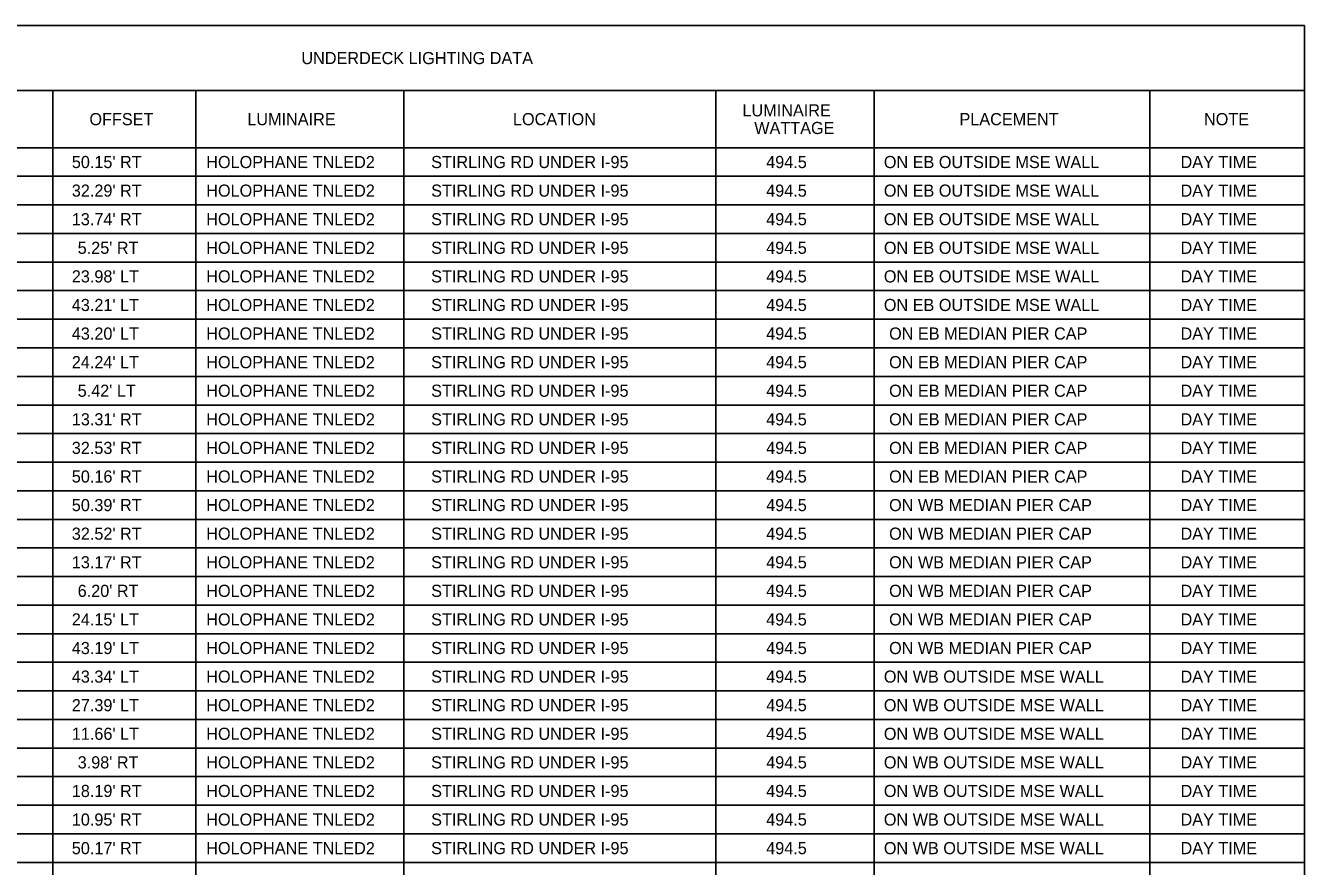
# Model space of a CAD drawing. Extents: x -816.7 to -800.9, y -2209.6 to -2187.8.
# Drawn here: x -810.38 to -803, y -2192.68 to -2187.82 of the extents above; entities that cross this region are included whole.
import ezdxf

# ---------------------------------------------------------------- set-up
doc = ezdxf.new("R2010")
doc.units = 0
for name, color, linetype in [('PlotBorder_dp', 7, 'Continuous'), ('SheetBorder_dp', 7, 'Continuous'), ('SheetLines_dp', 7, 'Continuous'), ('TextMinor', 7, 'Continuous')]:
    doc.layers.add(name, color=color, linetype=linetype)

msp = doc.modelspace()

# ---------------------------------------------------------------- linework, layer by layer
at = {"layer": 'PlotBorder_dp'}
for p, q in [((-810.2186, -2188.1983), (-810.2186, -2189.3533)), ((-810.2186, -2188.1983), (-810.2186, -2195.7208)), ((-809.3936, -2188.1983), (-809.3936, -2195.7208)), ((-809.3936, -2188.1983), (-809.3936, -2195.7208)), ((-808.1936, -2188.1983), (-808.1936, -2195.7208)), ((-808.1936, -2188.1983), (-808.1936, -2195.7208)), ((-806.3936, -2188.1983), (-806.3936, -2195.7208)), ((-806.3936, -2188.1983), (-806.3936, -2195.7208)), ((-805.4786, -2188.1983), (-805.4786, -2195.7208)), ((-805.4786, -2188.1983), (-805.4786, -2195.7208)), ((-813.0161, -2188.5283), (-803.8886, -2188.5283)), ((-810.2186, -2189.5183), (-810.2186, -2195.7208))]:
    msp.add_line(p, q, dxfattribs=at)
at = {"layer": 'SheetLines_dp'}
for p, q in [((-813.0161, -2187.8233), (-802.9961, -2187.8233)), ((-802.9961, -2187.8233), (-802.9961, -2195.7208)), ((-813.0161, -2188.1983), (-802.9961, -2188.1983)), ((-813.0161, -2188.1983), (-802.9961, -2188.1983)), ((-803.8886, -2188.1983), (-803.8886, -2195.7208)), ((-803.8886, -2188.1983), (-803.8886, -2195.7208))]:
    msp.add_line(p, q, dxfattribs=at)
at = {"layer": 'TextMinor'}
for p, q in [((-813.0161, -2188.5283), (-802.9961, -2188.5283)), ((-813.0161, -2188.6933), (-802.9961, -2188.6933)), ((-813.0161, -2188.6933), (-802.9961, -2188.6933)), ((-813.0161, -2188.8583), (-802.9961, -2188.8583)), ((-813.0161, -2188.8583), (-802.9961, -2188.8583)), ((-813.0161, -2189.0233), (-802.9961, -2189.0233)), ((-813.0161, -2189.0233), (-802.9961, -2189.0233)), ((-813.0161, -2189.1883), (-802.9961, -2189.1883)), ((-813.0161, -2189.1883), (-802.9961, -2189.1883)), ((-813.0161, -2189.3533), (-802.9961, -2189.3533)), ((-813.0161, -2189.3533), (-802.9961, -2189.3533)), ((-813.0161, -2189.5183), (-802.9961, -2189.5183)), ((-810.2186, -2189.5183), (-802.9961, -2189.5183)), ((-813.0161, -2189.6833), (-802.9961, -2189.6833)), ((-813.0161, -2189.6833), (-802.9961, -2189.6833)), ((-813.0161, -2189.8483), (-802.9961, -2189.8483)), ((-813.0161, -2189.8483), (-802.9961, -2189.8483)), ((-813.0161, -2190.0133), (-802.9961, -2190.0133)), ((-813.0161, -2190.0133), (-802.9961, -2190.0133)), ((-813.0161, -2190.1783), (-802.9961, -2190.1783)), ((-813.0161, -2190.1783), (-802.9961, -2190.1783)), ((-813.0161, -2190.3433), (-802.9961, -2190.3433)), ((-813.0161, -2190.3433), (-802.9961, -2190.3433)), ((-813.0161, -2190.5083), (-802.9961, -2190.5083)), ((-813.0161, -2190.5083), (-802.9961, -2190.5083)), ((-813.0161, -2190.6733), (-802.9961, -2190.6733)), ((-813.0161, -2190.6733), (-802.9961, -2190.6733)), ((-813.0161, -2190.8383), (-802.9961, -2190.8383)), ((-813.0161, -2190.8383), (-802.9961, -2190.8383)), ((-813.0161, -2191.0033), (-802.9961, -2191.0033)), ((-813.0161, -2191.0033), (-802.9961, -2191.0033)), ((-813.0161, -2191.1683), (-802.9961, -2191.1683)), ((-813.0161, -2191.1683), (-802.9961, -2191.1683)), ((-813.0161, -2191.3333), (-802.9961, -2191.3333)), ((-813.0161, -2191.3333), (-802.9961, -2191.3333)), ((-813.0161, -2191.4983), (-802.9961, -2191.4983)), ((-813.0161, -2191.4983), (-802.9961, -2191.4983)), ((-813.0161, -2191.6633), (-802.9961, -2191.6633)), ((-813.0161, -2191.6633), (-802.9961, -2191.6633)), ((-813.0161, -2191.8283), (-802.9961, -2191.8283)), ((-813.0161, -2191.8283), (-802.9961, -2191.8283)), ((-813.0161, -2191.9933), (-802.9961, -2191.9933)), ((-813.0161, -2191.9933), (-802.9961, -2191.9933)), ((-813.0161, -2192.1583), (-802.9961, -2192.1583)), ((-813.0161, -2192.1583), (-802.9961, -2192.1583)), ((-813.0161, -2192.3233), (-802.9961, -2192.3233)), ((-813.0161, -2192.3233), (-802.9961, -2192.3233)), ((-813.0161, -2192.4883), (-802.9961, -2192.4883)), ((-813.0161, -2192.4883), (-802.9961, -2192.4883)), ((-813.0161, -2192.6533), (-802.9961, -2192.6533)), ((-813.0161, -2192.6533), (-802.9961, -2192.6533))]:
    msp.add_line(p, q, dxfattribs=at)

# ---------------------------------------------------------------- texts
at = {"layer": 'SheetBorder_dp'}
for s, p in [('UNDERDECK LIGHTING DATA', (-808.7843, -2188.0458)), ('LUMINAIRE', (-806.2388, -2188.3473)), ('OFFSET', (-810.0076, -2188.3983)), ('LUMINAIRE', (-809.0963, -2188.3983)), ('LOCATION', (-807.5633, -2188.3983)), ('PLACEMENT', (-804.9867, -2188.3983)), ('NOTE', (-803.5756, -2188.3983)), ('WATTAGE', (-806.171, -2188.4493)), ("50.15' RT", (-810.1092, -2188.6458)), ('HOLOPHANE TNLED2', (-809.3332, -2188.6458)), ('STIRLING RD UNDER I-95', (-808.0355, -2188.6458)), ('494.5', (-806.1021, -2188.6458)), ('ON EB OUTSIDE MSE WALL', (-805.4232, -2188.6458)), ('DAY TIME', (-803.7111, -2188.6458)), ("32.29' RT", (-810.1092, -2188.8108)), ('HOLOPHANE TNLED2', (-809.3332, -2188.8108)), ('STIRLING RD UNDER I-95', (-808.0355, -2188.8108)), ('494.5', (-806.1021, -2188.8108)), ('ON EB OUTSIDE MSE WALL', (-805.4232, -2188.8108)), ('DAY TIME', (-803.7111, -2188.8108)), ("13.74' RT", (-810.1092, -2188.9758)), ('HOLOPHANE TNLED2', (-809.3332, -2188.9758)), ('STIRLING RD UNDER I-95', (-808.0355, -2188.9758)), ('494.5', (-806.1021, -2188.9758)), ('ON EB OUTSIDE MSE WALL', (-805.4232, -2188.9758)), ('DAY TIME', (-803.7111, -2188.9758)), ("5.25' RT", (-810.0753, -2189.1408)), ('HOLOPHANE TNLED2', (-809.3332, -2189.1408)), ('STIRLING RD UNDER I-95', (-808.0355, -2189.1408)), ('494.5', (-806.1021, -2189.1408)), ('ON EB OUTSIDE MSE WALL', (-805.4232, -2189.1408)), ('DAY TIME', (-803.7111, -2189.1408)), ("23.98' LT", (-810.1092, -2189.3058)), ('HOLOPHANE TNLED2', (-809.3332, -2189.3058)), ('STIRLING RD UNDER I-95', (-808.0355, -2189.3058)), ('494.5', (-806.1021, -2189.3058)), ('ON EB OUTSIDE MSE WALL', (-805.4232, -2189.3058)), ('DAY TIME', (-803.7111, -2189.3058)), ("43.21' LT", (-810.1092, -2189.4708)), ('HOLOPHANE TNLED2', (-809.3332, -2189.4708)), ('STIRLING RD UNDER I-95', (-808.0355, -2189.4708)), ('494.5', (-806.1021, -2189.4708)), ('ON EB OUTSIDE MSE WALL', (-805.4232, -2189.4708)), ('DAY TIME', (-803.7111, -2189.4708)), ("43.20' LT", (-810.1092, -2189.6358)), ('HOLOPHANE TNLED2', (-809.3332, -2189.6358)), ('STIRLING RD UNDER I-95', (-808.0355, -2189.6358)), ('494.5', (-806.1021, -2189.6358)), ('ON EB MEDIAN PIER CAP', (-805.3928, -2189.6358)), ('DAY TIME', (-803.7111, -2189.6358)), ("24.24' LT", (-810.1092, -2189.8008)), ('HOLOPHANE TNLED2', (-809.3332, -2189.8008)), ('STIRLING RD UNDER I-95', (-808.0355, -2189.8008)), ('494.5', (-806.1021, -2189.8008)), ('ON EB MEDIAN PIER CAP', (-805.3928, -2189.8008)), ('DAY TIME', (-803.7111, -2189.8008)), ("5.42' LT", (-810.0753, -2189.9658)), ('HOLOPHANE TNLED2', (-809.3332, -2189.9658)), ('STIRLING RD UNDER I-95', (-808.0355, -2189.9658)), ('494.5', (-806.1021, -2189.9658)), ('ON EB MEDIAN PIER CAP', (-805.3928, -2189.9658)), ('DAY TIME', (-803.7111, -2189.9658)), ("13.31' RT", (-810.1092, -2190.1308)), ('HOLOPHANE TNLED2', (-809.3332, -2190.1308)), ('STIRLING RD UNDER I-95', (-808.0355, -2190.1308)), ('494.5', (-806.1021, -2190.1308)), ('ON EB MEDIAN PIER CAP', (-805.3928, -2190.1308)), ('DAY TIME', (-803.7111, -2190.1308)), ("32.53' RT", (-810.1092, -2190.2958)), ('HOLOPHANE TNLED2', (-809.3332, -2190.2958)), ('STIRLING RD UNDER I-95', (-808.0355, -2190.2958)), ('494.5', (-806.1021, -2190.2958)), ('ON EB MEDIAN PIER CAP', (-805.3928, -2190.2958)), ('DAY TIME', (-803.7111, -2190.2958)), ("50.16' RT", (-810.1092, -2190.4608)), ('HOLOPHANE TNLED2', (-809.3332, -2190.4608)), ('STIRLING RD UNDER I-95', (-808.0355, -2190.4608)), ('494.5', (-806.1021, -2190.4608)), ('ON EB MEDIAN PIER CAP', (-805.3928, -2190.4608)), ('DAY TIME', (-803.7111, -2190.4608)), ("50.39' RT", (-810.1092, -2190.6258)), ('HOLOPHANE TNLED2', (-809.3332, -2190.6258)), ('STIRLING RD UNDER I-95', (-808.0355, -2190.6258)), ('494.5', (-806.1021, -2190.6258)), ('ON WB MEDIAN PIER CAP', (-805.3928, -2190.6258)), ('DAY TIME', (-803.7111, -2190.6258)), ("32.52' RT", (-810.1092, -2190.7908)), ('HOLOPHANE TNLED2', (-809.3332, -2190.7908)), ('STIRLING RD UNDER I-95', (-808.0355, -2190.7908)), ('494.5', (-806.1021, -2190.7908)), ('ON WB MEDIAN PIER CAP', (-805.3928, -2190.7908)), ('DAY TIME', (-803.7111, -2190.7908)), ("13.17' RT", (-810.1092, -2190.9558)), ('HOLOPHANE TNLED2', (-809.3332, -2190.9558)), ('STIRLING RD UNDER I-95', (-808.0355, -2190.9558)), ('494.5', (-806.1021, -2190.9558)), ('ON WB MEDIAN PIER CAP', (-805.3928, -2190.9558)), ('DAY TIME', (-803.7111, -2190.9558)), ("6.20' RT", (-810.0753, -2191.1208)), ('HOLOPHANE TNLED2', (-809.3332, -2191.1208)), ('STIRLING RD UNDER I-95', (-808.0355, -2191.1208)), ('494.5', (-806.1021, -2191.1208)), ('ON WB MEDIAN PIER CAP', (-805.3928, -2191.1208)), ('DAY TIME', (-803.7111, -2191.1208)), ("24.15' LT", (-810.1092, -2191.2858)), ('HOLOPHANE TNLED2', (-809.3332, -2191.2858)), ('STIRLING RD UNDER I-95', (-808.0355, -2191.2858)), ('494.5', (-806.1021, -2191.2858)), ('ON WB MEDIAN PIER CAP', (-805.3928, -2191.2858)), ('DAY TIME', (-803.7111, -2191.2858)), ("43.19' LT", (-810.1092, -2191.4508)), ('HOLOPHANE TNLED2', (-809.3332, -2191.4508)), ('STIRLING RD UNDER I-95', (-808.0355, -2191.4508)), ('494.5', (-806.1021, -2191.4508)), ('ON WB MEDIAN PIER CAP', (-805.3928, -2191.4508)), ('DAY TIME', (-803.7111, -2191.4508)), ("43.34' LT", (-810.1092, -2191.6158)), ('HOLOPHANE TNLED2', (-809.3332, -2191.6158)), ('STIRLING RD UNDER I-95', (-808.0355, -2191.6158)), ('494.5', (-806.1021, -2191.6158)), ('ON WB OUTSIDE MSE WALL', (-805.4232, -2191.6158)), ('DAY TIME', (-803.7111, -2191.6158)), ("27.39' LT", (-810.1092, -2191.7808)), ('HOLOPHANE TNLED2', (-809.3332, -2191.7808)), ('STIRLING RD UNDER I-95', (-808.0355, -2191.7808)), ('494.5', (-806.1021, -2191.7808)), ('ON WB OUTSIDE MSE WALL', (-805.4232, -2191.7808)), ('DAY TIME', (-803.7111, -2191.7808)), ("11.66' LT", (-810.1092, -2191.9458)), ('HOLOPHANE TNLED2', (-809.3332, -2191.9458)), ('STIRLING RD UNDER I-95', (-808.0355, -2191.9458)), ('494.5', (-806.1021, -2191.9458)), ('ON WB OUTSIDE MSE WALL', (-805.4232, -2191.9458)), ('DAY TIME', (-803.7111, -2191.9458)), ("3.98' RT", (-810.0753, -2192.1108)), ('HOLOPHANE TNLED2', (-809.3332, -2192.1108)), ('STIRLING RD UNDER I-95', (-808.0355, -2192.1108)), ('494.5', (-806.1021, -2192.1108)), ('ON WB OUTSIDE MSE WALL', (-805.4232, -2192.1108)), ('DAY TIME', (-803.7111, -2192.1108)), ("18.19' RT", (-810.1092, -2192.2758)), ('HOLOPHANE TNLED2', (-809.3332, -2192.2758)), ('STIRLING RD UNDER I-95', (-808.0355, -2192.2758)), ('494.5', (-806.1021, -2192.2758)), ('ON WB OUTSIDE MSE WALL', (-805.4232, -2192.2758)), ('DAY TIME', (-803.7111, -2192.2758)), ("10.95' RT", (-810.1092, -2192.4408)), ('HOLOPHANE TNLED2', (-809.3332, -2192.4408)), ('STIRLING RD UNDER I-95', (-808.0355, -2192.4408)), ('494.5', (-806.1021, -2192.4408)), ('ON WB OUTSIDE MSE WALL', (-805.4232, -2192.4408)), ('DAY TIME', (-803.7111, -2192.4408)), ("50.17' RT", (-810.1092, -2192.6058)), ('HOLOPHANE TNLED2', (-809.3332, -2192.6058)), ('STIRLING RD UNDER I-95', (-808.0355, -2192.6058)), ('494.5', (-806.1021, -2192.6058)), ('ON WB OUTSIDE MSE WALL', (-805.4232, -2192.6058)), ('DAY TIME', (-803.7111, -2192.6058))]:
    msp.add_text(s, height=0.07, dxfattribs=at).set_placement(p)

doc.saveas('drawing.dxf')
